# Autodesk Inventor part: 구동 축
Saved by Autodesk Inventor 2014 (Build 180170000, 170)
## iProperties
Created: 2025-09
Part Number: 구동 축
Material: 일반
Document SubType Name: Modeling
Designer: dg
Density: 1 g/cm^3
Appearance: 기본값
Author: dg
Author: jhkim
Creation Date: 2025-09-02
Sending System: Autodesk Inventor 2026
Preprocessor: ST-DEVELOPER v20.1
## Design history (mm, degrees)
node "구동 축1"
node "솔리드1"
node "기준1"
